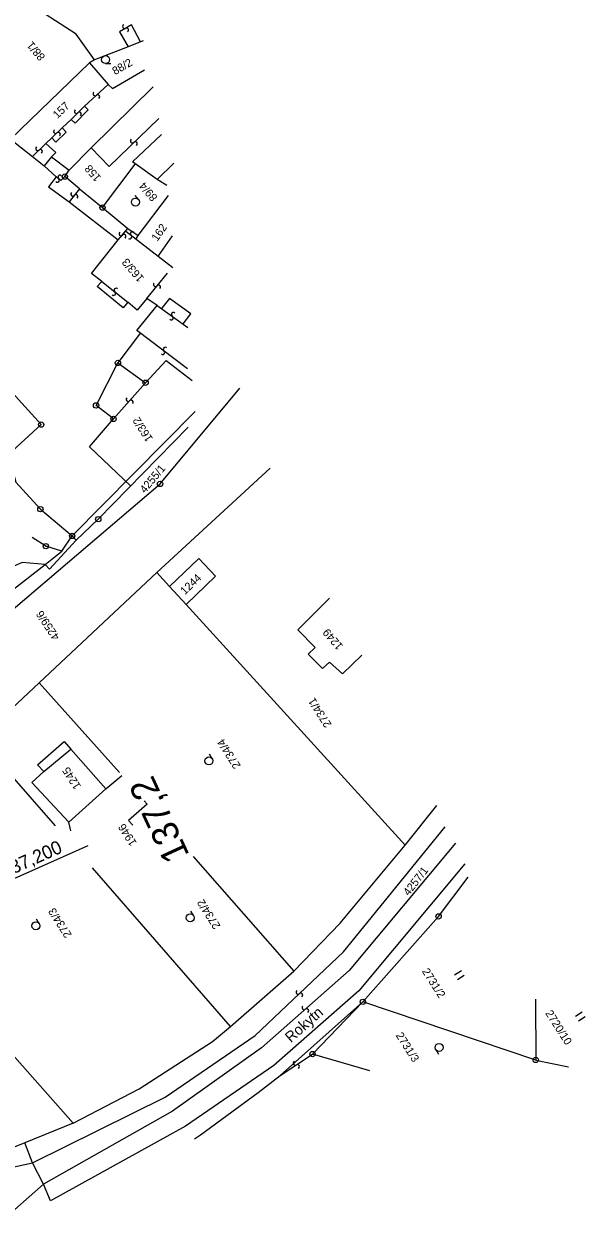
# Model space of a CAD drawing. Extents: x -658910 to -658078, y -1170373 to -1169331.
# Drawn here: x -658330.6 to -658225.4, y -1170347.2 to -1170123.2 of the extents above; entities that cross this region are included whole.
import ezdxf

# ---------------------------------------------------------------- set-up
doc = ezdxf.new("R2010")
doc.units = 0
for name, color, linetype in [('Vrstva 1', 7, 'Continuous'), ('Vrstva 38', 7, 'Continuous'), ('Vrstva 39', 7, 'Continuous'), ('Vrstva 7', 7, 'Continuous'), ('Vrstva 8', 7, 'Continuous'), ('Vrstva 9', 7, 'Continuous')]:
    doc.layers.add(name, color=color, linetype=linetype)

msp = doc.modelspace()

# ---------------------------------------------------------------- linework, layer by layer
at = {"layer": 'Vrstva 1'}
for points in [[(-658370.27, -1170208.691), (-658365.012, -1170214.699), (-658352.621, -1170229.211), (-658347.77, -1170235.02), (-658358.41, -1170245.469), (-658373.641, -1170258.449), (-658367.441, -1170262.461), (-658359.102, -1170278.891), (-658351.488, -1170290.83), (-658344.789, -1170302.82), (-658321.379, -1170329.199), (-658330.469, -1170332.85)], [(-658330.469, -1170332.85), (-658356.398, -1170343.289), (-658366.66, -1170318.129), (-658369.211, -1170312.75), (-658376.602, -1170296.77), (-658379.789, -1170292.191), (-658390.738, -1170282.121), (-658389.18, -1170276.711), (-658384.27, -1170264.699), (-658395.621, -1170235.01), (-658403.5, -1170214.23)]]:
    msp.add_lwpolyline(points, dxfattribs=at)
at = {"layer": 'Vrstva 38'}
msp.add_lwpolyline([(-658363.015, -1170296.942), (-658360.859, -1170295.983), (-658318.569, -1170277.155)], dxfattribs=at)
at = {"layer": 'Vrstva 8'}
for p, q in [((-658323.019, -1170151.83), (-658322.919, -1170151.83)), ((-658323.019, -1170151.83), (-658322.919, -1170151.83)), ((-658315.96, -1170157.641), (-658315.86, -1170157.641)), ((-658315.96, -1170157.641), (-658315.86, -1170157.641)), ((-658313.062, -1170186.74), (-658312.962, -1170186.74)), ((-658313.062, -1170186.74), (-658312.962, -1170186.74)), ((-658307.87, -1170190.461), (-658307.77, -1170190.461)), ((-658307.87, -1170190.461), (-658307.77, -1170190.461)), ((-658317.171, -1170194.711), (-658317.071, -1170194.711)), ((-658298.551, -1170195.871), (-658298.551, -1170195.871)), ((-658327.46, -1170198.301), (-658327.36, -1170198.301)), ((-658313.89, -1170197.23), (-658313.79, -1170197.23)), ((-658313.89, -1170197.23), (-658313.79, -1170197.23)), ((-658305.171, -1170209.41), (-658305.071, -1170209.41)), ((-658327.601, -1170214.141), (-658327.501, -1170214.141)), ((-658316.741, -1170216.01), (-658316.641, -1170216.01)), ((-658321.64, -1170219.16), (-658321.54, -1170219.16)), ((-658321.64, -1170219.16), (-658321.54, -1170219.16)), ((-658321.64, -1170219.16), (-658321.54, -1170219.16)), ((-658321.64, -1170219.16), (-658321.54, -1170219.16)), ((-658326.57, -1170221.08), (-658326.47, -1170221.08)), ((-658252.941, -1170290.449), (-658252.841, -1170290.449)), ((-658267.116, -1170306.418), (-658267.063, -1170306.503)), ((-658267.116, -1170306.418), (-658267.063, -1170306.503)), ((-658276.589, -1170316.25), (-658276.489, -1170316.25)), ((-658276.589, -1170316.25), (-658276.489, -1170316.25)), ((-658234.717, -1170317.316), (-658234.664, -1170317.401)), ((-658234.717, -1170317.316), (-658234.664, -1170317.401))]:
    msp.add_line(p, q, dxfattribs=at)
for points in [[(-658308.309, -1170126.391), (-658308.77, -1170126.58), (-658310.441, -1170123.379), (-658312.691, -1170124.711), (-658311.09, -1170127.5), (-658317.41, -1170129.961), (-658320.859, -1170125.121), (-658328.59, -1170120.141)], [(-658308.77, -1170126.58), (-658311.09, -1170127.5)], [(-658318.371, -1170130.531), (-658333.141, -1170144.789), (-658329.059, -1170148.059), (-658326.859, -1170149.789), (-658324.578, -1170151.859), (-658326, -1170153.76), (-658322.172, -1170156.539), (-658312.941, -1170163.66), (-658311.129, -1170161.539), (-658309.211, -1170162.891), (-658303.559, -1170155.359)], [(-658317.41, -1170129.961), (-658318.371, -1170130.531), (-658314.82, -1170134.559), (-658314.02, -1170135.309), (-658308.012, -1170131.85)], [(-658384.859, -1170135.77), (-658343.121, -1170180.961), (-658327.41, -1170198.301), (-658333.559, -1170203.879), (-658332.172, -1170209.1), (-658327.551, -1170214.141), (-658321.59, -1170219.16), (-658320.828, -1170219.93), (-658325.852, -1170225.359), (-658326.648, -1170224.5), (-658330.98, -1170224.109), (-658334.898, -1170225.871), (-658347.059, -1170235.289), (-658344.5, -1170238.391), (-658326.648, -1170224.5)], [(-658314.82, -1170134.559), (-658319.289, -1170138.621), (-658318.59, -1170139.309), (-658321.031, -1170141.789), (-658321.789, -1170141.141), (-658323.461, -1170142.711), (-658322.699, -1170143.48), (-658324.66, -1170145.379), (-658325.43, -1170144.58), (-658326.551, -1170145.641), (-658324.648, -1170147.34), (-658325.461, -1170148.109), (-658322.18, -1170150.629), (-658318, -1170146.42)], [(-658305.371, -1170140.93), (-658314.68, -1170149.91), (-658318, -1170146.42), (-658306.398, -1170135.02)], [(-658319.289, -1170138.621), (-658321.789, -1170141.141)], [(-658323.461, -1170142.711), (-658325.43, -1170144.58)], [(-658305.68, -1170152.4), (-658310.289, -1170149.031), (-658304.871, -1170143.92)], [(-658326.551, -1170145.641), (-658329.059, -1170148.059)], [(-658325.461, -1170148.109), (-658326.859, -1170149.789)], [(-658315.91, -1170157.641), (-658309.762, -1170149.51)], [(-658303.871, -1170153.48), (-658305.68, -1170152.4), (-658302.531, -1170149.33)], [(-658322.969, -1170151.83), (-658323.691, -1170152.57), (-658324.578, -1170151.859)], [(-658320.211, -1170154.141), (-658322.969, -1170151.83), (-658322.18, -1170150.629)], [(-658320.211, -1170154.141), (-658322.172, -1170156.539)], [(-658320.211, -1170154.141), (-658315.91, -1170157.641), (-658311.129, -1170161.539)], [(-658311.559, -1170162.07), (-658302.75, -1170168.84)], [(-658309.609, -1170163.5), (-658309.211, -1170162.891)], [(-658305.398, -1170166.66), (-658302.809, -1170162.9)], [(-658307.609, -1170174.641), (-658309.379, -1170176.85), (-658311.148, -1170175.371), (-658312, -1170176.441), (-658316.93, -1170172.449), (-658316.039, -1170171.469), (-658317.98, -1170169.961), (-658312.941, -1170163.66)], [(-658305.68, -1170176), (-658307.609, -1170174.641), (-658303.75, -1170169.92)], [(-658316.039, -1170171.469), (-658311.148, -1170175.371)], [(-658299.98, -1170187.85), (-658309.449, -1170180.68), (-658305.68, -1170176), (-658299.93, -1170180.129)], [(-658300.781, -1170179.4), (-658299.34, -1170177.551), (-658303.34, -1170174.641), (-658304.852, -1170176.57)], [(-658308.781, -1170181.1), (-658313.012, -1170186.74)], [(-658310.66, -1170209.781), (-658318.352, -1170202.449), (-658313.84, -1170197.23), (-658317.121, -1170194.711), (-658313.012, -1170186.74), (-658307.82, -1170190.461), (-658313.84, -1170197.23)], [(-658307.82, -1170190.461), (-658303.988, -1170186.289), (-658299.07, -1170190.02)], [(-658367.441, -1170262.461), (-658305.121, -1170209.41), (-658290.129, -1170191.49)], [(-658298.551, -1170195.871), (-658321.59, -1170219.16)], [(-658299.871, -1170198.77), (-658316.691, -1170216.01), (-658320.828, -1170219.93)], [(-658259.148, -1170277.1), (-658300.238, -1170232), (-658294.719, -1170226.719), (-658297.852, -1170223.4), (-658303.371, -1170228.621), (-658305.75, -1170225.99), (-658284.5, -1170206.49)], [(-658326.648, -1170224.5), (-658323.539, -1170221.99), (-658321.59, -1170219.16)], [(-658323.539, -1170221.99), (-658326.52, -1170221.08), (-658329.091, -1170219.461)], [(-658305.75, -1170225.99), (-658327.789, -1170246.691), (-658312.748, -1170263.497)], [(-658303.371, -1170228.621), (-658300.238, -1170232)], [(-658267.27, -1170241.52), (-658270.898, -1170245), (-658273.352, -1170242.789), (-658274.629, -1170243.98), (-658277.32, -1170241.32), (-658276.012, -1170240.059), (-658279.309, -1170236.73), (-658273.359, -1170230.801)], [(-658324.686, -1170273.482), (-658339.031, -1170257.199), (-658327.789, -1170246.691)], [(-658321.85, -1170274.443), (-658322.219, -1170272.781), (-658329.148, -1170265.379), (-658326.898, -1170263.32), (-658328.121, -1170262.07), (-658323.09, -1170257.65), (-658321.871, -1170259.09), (-658315.309, -1170266.539), (-658312.27, -1170264.031)], [(-658326.898, -1170263.32), (-658321.871, -1170259.09)], [(-658315.309, -1170266.539), (-658322.219, -1170272.781)], [(-658321.379, -1170329.199), (-658309, -1170322.74), (-658295.301, -1170313.871), (-658291.91, -1170311.051), (-658280.059, -1170300.74), (-658271.371, -1170291.75), (-658259.148, -1170277.1), (-658253.199, -1170269.68)], [(-658308.117, -1170268.768), (-658307.52, -1170269.449), (-658311, -1170272.461), (-658310.206, -1170273.348)], [(-658248, -1170280.629), (-658267.859, -1170304.371), (-658283.789, -1170318.391), (-658300.328, -1170329.73), (-658325.629, -1170343.76), (-658326.949, -1170340.621), (-658332.328, -1170345.4), (-658336.27, -1170347.17), (-658339.488, -1170339.891), (-658335.691, -1170338.07), (-658329.039, -1170336.641), (-658304.129, -1170324.309), (-658287.289, -1170312.77), (-658270.719, -1170297.09), (-658251.66, -1170273.66)], [(-658249.73, -1170276.699), (-658269.691, -1170300.58), (-658286.07, -1170315.109), (-658302.762, -1170326.949), (-658326.949, -1170340.621), (-658329.039, -1170336.641), (-658330.469, -1170332.85)], [(-658298.918, -1170279.203), (-658280.059, -1170300.74)], [(-658291.91, -1170311.051), (-658317.769, -1170281.375)], [(-658298.66, -1170332.141), (-658297.559, -1170331.41), (-658286.75, -1170323.461), (-658282.57, -1170320.289), (-658276.539, -1170316.25), (-658267.09, -1170306.461), (-658252.891, -1170290.449), (-658247.328, -1170283.07)], [(-658234.691, -1170317.359), (-658267.09, -1170306.461), (-658282.57, -1170320.289)], [(-658234.73, -1170305.969), (-658234.691, -1170317.359), (-658228.52, -1170318.621)], [(-658265.809, -1170319.376), (-658276.539, -1170316.25)]]:
    msp.add_lwpolyline(points, dxfattribs=at)
for centre in [(-658322.969, -1170151.83), (-658322.969, -1170151.83), (-658315.91, -1170157.641), (-658315.91, -1170157.641), (-658313.012, -1170186.74), (-658313.012, -1170186.74), (-658307.82, -1170190.461), (-658307.82, -1170190.461), (-658317.121, -1170194.711), (-658313.84, -1170197.23), (-658313.84, -1170197.23), (-658327.41, -1170198.301), (-658305.121, -1170209.41), (-658327.551, -1170214.141), (-658316.691, -1170216.01), (-658321.59, -1170219.16), (-658321.59, -1170219.16), (-658321.59, -1170219.16), (-658321.59, -1170219.16), (-658326.52, -1170221.08), (-658252.891, -1170290.449), (-658267.09, -1170306.461), (-658267.09, -1170306.461), (-658276.539, -1170316.25), (-658276.539, -1170316.25), (-658234.691, -1170317.359), (-658234.691, -1170317.359)]:
    msp.add_circle(centre, 0.499, dxfattribs=at)
for centre, radius, start, end in [((-658311.757, -1170123.724), 0.376, 113.61296, 299.92409), ((-658311.378, -1170124.375), 0.377, 292.93692, 120.60013), ((-658317.3, -1170136.308), 0.376, 125.27411, 311.58524), ((-658316.797, -1170136.868), 0.377, 304.59806, 132.26128), ((-658320.803, -1170139.61), 0.376, 128.23053, 314.54166), ((-658320.271, -1170140.144), 0.377, 307.55449, 135.2177), ((-658324.696, -1170143.364), 0.376, 126.37048, 312.68161), ((-658324.182, -1170143.914), 0.377, 305.69444, 133.35765), ((-658310.278, -1170145.145), 0.376, 126.97229, 313.28342), ((-658309.758, -1170145.691), 0.377, 306.29625, 133.95946), ((-658328.059, -1170146.575), 0.376, 126.96059, 313.27173), ((-658327.539, -1170147.121), 0.377, 306.28455, 133.94776), ((-658323.891, -1170151.926), 0.376, 44.58567, 230.89681), ((-658324.363, -1170152.514), 0.377, 223.90963, 51.57285), ((-658321.479, -1170155.098), 0.376, 133.75097, 320.06211), ((-658320.899, -1170155.578), 0.377, 313.07493, 140.73814), ((-658312.433, -1170162.55), 0.376, 130.26598, 316.57712), ((-658311.883, -1170163.064), 0.377, 309.58994, 137.25316), ((-658310.784, -1170163.135), 0.376, 225.30535, 51.61648), ((-658310.32, -1170162.542), 0.377, 44.62931, 232.29252), ((-658305.968, -1170172.039), 0.376, 133.79136, 320.10249), ((-658305.388, -1170172.519), 0.377, 313.11532, 140.77853), ((-658313.824, -1170173.714), 0.377, 223.80329, 51.46651), ((-658313.352, -1170173.128), 0.376, 44.47933, 230.79047), ((-658303.035, -1170178.288), 0.377, 227.44358, 55.10679), ((-658302.601, -1170177.673), 0.376, 48.11962, 234.43076), ((-658304.608, -1170184.778), 0.377, 224.85897, 52.52218), ((-658304.146, -1170184.184), 0.376, 45.53501, 231.84614), ((-658311.098, -1170193.586), 0.376, 131.41122, 317.72235), ((-658310.538, -1170194.09), 0.377, 310.73518, 138.39839), ((-658279.255, -1170304.653), 0.376, 126.45825, 312.76938), ((-658278.741, -1170305.203), 0.377, 305.78221, 133.44542), ((-658278.125, -1170307.565), 0.376, 124.61549, 310.92662), ((-658277.628, -1170308.131), 0.377, 303.93944, 131.60266), ((-658279.756, -1170317.954), 0.376, 116.78894, 303.10008), ((-658279.341, -1170318.583), 0.377, 296.1129, 123.77612)]:
    msp.add_arc(centre, radius, start, end, dxfattribs=at)
at = {"layer": 'Vrstva 9'}
for p, q in [((-658315.328, -1170130.66), (-658314.328, -1170130.66)), ((-658309.152, -1170156.118), (-658309.803, -1170155.359)), ((-658295.325, -1170260.899), (-658295.863, -1170260.056)), ((-658298.83, -1170290.31), (-658299.368, -1170289.467)), ((-658327.761, -1170291.814), (-658328.299, -1170290.971)), ((-658248.632, -1170300.643), (-658249.897, -1170301.449)), ((-658249.629, -1170301.871), (-658249.629, -1170301.871)), ((-658249.36, -1170302.292), (-658248.095, -1170301.486)), ((-658225.964, -1170308.393), (-658227.229, -1170309.199)), ((-658226.961, -1170309.621), (-658226.961, -1170309.621)), ((-658226.692, -1170310.042), (-658225.427, -1170309.236)), ((-658253.43, -1170315.42), (-658252.892, -1170316.263))]:
    msp.add_line(p, q, dxfattribs=at)
for centre in [(-658315.328, -1170129.91), (-658309.722, -1170156.606), (-658295.958, -1170261.303), (-658299.463, -1170290.714), (-658328.394, -1170292.218), (-658252.797, -1170315.016)]:
    msp.add_circle(centre, 0.75, dxfattribs=at)

# ---------------------------------------------------------------- texts
at = {"layer": 'Vrstva 39'}
msp.add_text('km 137,200', height=2.5, rotation=23.99875, dxfattribs=at).set_placement((-658339.193, -1170285.488))
at = {"layer": 'Vrstva 7'}
msp.add_text('137,2', height=4.999, rotation=114.8242, dxfattribs=at).set_placement((-658299.525, -1170278.967))
at = {"layer": 'Vrstva 9'}
for s, height, rotation, p in [('88/1', 1.5, 130.49568, (-658326.55, -1170129.335)), ('88/2', 1.5, 29.92897, (-658313.539, -1170132.84)), ('157', 1.5, 43.32328, (-658324.371, -1170141.07)), ('158', 1.5, 130.49568, (-658316.07, -1170152.001)), ('89/4', 1.5, 130.49568, (-658305.496, -1170155.679)), ('162', 1.5, 55.38402, (-658305.621, -1170164.08)), ('163/3', 1.5, 130.49568, (-658308.008, -1170170.812)), ('163/2', 1.5, 122.51061, (-658306.388, -1170200.939)), ('4255/1', 1.5, 50.07729, (-658307.93, -1170211.27)), ('1244', 1.5, 43.70441, (-658300.461, -1170230.281)), ('4259/6', 1.5, 123.16753, (-658323.856, -1170238.116)), ('1249', 1.5, 130.49568, (-658270.712, -1170239.754)), ('2734/1', 1.5, 122.51061, (-658272.889, -1170254.481)), ('2734/4', 1.5, 122.51061, (-658289.938, -1170262.197)), ('1245', 1.5, 122.51061, (-658319.876, -1170266.054)), ('1946', 1.5, 122.51061, (-658309.411, -1170276.669)), ('4257/1', 1.5, 52.06143, (-658258.495, -1170286.709)), ('2734/2', 1.5, 122.51061, (-658293.721, -1170292.232)), ('2734/3', 1.5, 122.51061, (-658321.614, -1170293.875)), ('2731/2', 1.5, 302.51061, (-658256.07, -1170300.74)), ('Rokytn\xa0', 2, 41.36947, (-658280.602, -1170314.211)), ('2720/10', 1.5, 302.51061, (-658232.949, -1170308.59)), ('2731/3', 1.5, 302.51061, (-658260.988, -1170312.75))]:
    msp.add_text(s, height=height, rotation=rotation, dxfattribs=at).set_placement(p)

doc.saveas('drawing.dxf')
